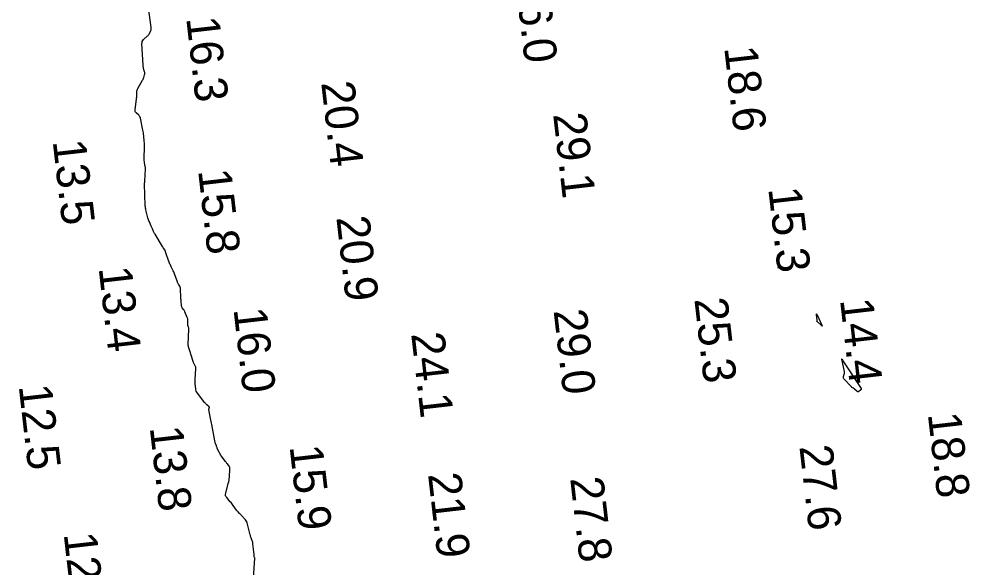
# Model space of a CAD drawing. Extents: x 1023796 to 1112670, y 656573 to 837340.
# Drawn here: x 1109716.8 to 1109860.7, y 681529.2 to 681612.4 of the extents above; entities that cross this region are included whole.
import ezdxf

# ---------------------------------------------------------------- set-up
doc = ezdxf.new("R2010")
doc.units = 0
doc.layers.add('V-CHAN-CONT-15FT', color=7, linetype='Continuous')
doc.layers.add('V-TOPO-SOUN', color=7, linetype='Continuous')

msp = doc.modelspace()

# ---------------------------------------------------------------- linework, layer by layer
at = {"layer": 'V-CHAN-CONT-15FT'}
msp.add_lwpolyline([(1109752.25, 681526.93), (1109752.47, 681530.72), (1109752.47, 681530.75), (1109752.47, 681530.78), (1109752.46, 681530.8), (1109752.45, 681530.83), (1109752.4, 681530.92), (1109752.39, 681530.95), (1109752.38, 681530.97), (1109752.38, 681531), (1109752.38, 681531.03), (1109752.39, 681531.15), (1109752.39, 681531.18), (1109752.39, 681531.21), (1109752.39, 681531.24), (1109752.39, 681531.27), (1109752.2, 681532.92), (1109752.18, 681533.03), (1109752.16, 681533.15), (1109752.12, 681533.26), (1109752.08, 681533.37), (1109751.91, 681533.81), (1109751.87, 681533.92), (1109751.83, 681534.03), (1109751.8, 681534.14), (1109751.77, 681534.26), (1109751.39, 681535.89), (1109751.34, 681536.07), (1109751.26, 681536.23), (1109751.17, 681536.39), (1109751.05, 681536.54), (1109750.4, 681537.26), (1109750.34, 681537.32), (1109750.29, 681537.38), (1109750.23, 681537.44), (1109750.17, 681537.5), (1109749.94, 681537.73), (1109749.88, 681537.79), (1109749.83, 681537.85), (1109749.77, 681537.91), (1109749.72, 681537.98), (1109749.2, 681538.71), (1109749.09, 681538.85), (1109748.98, 681538.99), (1109748.87, 681539.13), (1109748.76, 681539.26), (1109748.22, 681539.89), (1109748.11, 681540.05), (1109748.05, 681540.21), (1109748.04, 681540.39), (1109748.07, 681540.57), (1109748.46, 681542.04), (1109748.52, 681542.28), (1109748.57, 681542.52), (1109748.6, 681542.76), (1109748.62, 681543.01), (1109748.7, 681544.26), (1109748.7, 681544.36), (1109748.68, 681544.46), (1109748.64, 681544.56), (1109748.58, 681544.65), (1109748.32, 681545), (1109748.26, 681545.08), (1109748.19, 681545.17), (1109748.13, 681545.26), (1109748.06, 681545.34), (1109747.4, 681546.22), (1109747.31, 681546.34), (1109747.23, 681546.47), (1109747.16, 681546.6), (1109747.09, 681546.73), (1109746.8, 681547.37), (1109746.76, 681547.46), (1109746.72, 681547.55), (1109746.68, 681547.64), (1109746.65, 681547.73), (1109746.52, 681548.1), (1109746.49, 681548.19), (1109746.46, 681548.28), (1109746.43, 681548.38), (1109746.41, 681548.47), (1109745.96, 681550.95), (1109745.92, 681551.19), (1109745.87, 681551.42), (1109745.83, 681551.66), (1109745.79, 681551.89), (1109745.53, 681553.22), (1109745.52, 681553.26), (1109745.52, 681553.29), (1109745.53, 681553.33), (1109745.54, 681553.36), (1109745.58, 681553.51), (1109745.59, 681553.54), (1109745.59, 681553.57), (1109745.57, 681553.6), (1109745.55, 681553.63), (1109745.19, 681553.96), (1109745.12, 681554.03), (1109745.05, 681554.1), (1109744.99, 681554.17), (1109744.93, 681554.24), (1109743.79, 681555.71), (1109743.69, 681555.86), (1109743.62, 681556.02), (1109743.56, 681556.19), (1109743.53, 681556.37), (1109743.47, 681557.1), (1109743.45, 681557.28), (1109743.45, 681557.46), (1109743.45, 681557.64), (1109743.46, 681557.83), (1109743.57, 681559.4), (1109743.57, 681559.49), (1109743.55, 681559.57), (1109743.53, 681559.65), (1109743.49, 681559.73), (1109743.32, 681560.03), (1109743.28, 681560.1), (1109743.25, 681560.18), (1109743.22, 681560.26), (1109743.19, 681560.34), (1109742.8, 681561.61), (1109742.76, 681561.73), (1109742.72, 681561.86), (1109742.68, 681561.98), (1109742.64, 681562.1), (1109742.48, 681562.59), (1109742.45, 681562.71), (1109742.42, 681562.84), (1109742.41, 681562.96), (1109742.41, 681563.09), (1109742.51, 681565.41), (1109742.51, 681565.48), (1109742.5, 681565.55), (1109742.49, 681565.62), (1109742.46, 681565.69), (1109742.36, 681565.96), (1109742.33, 681566.03), (1109742.32, 681566.1), (1109742.31, 681566.17), (1109742.31, 681566.24), (1109742.33, 681566.76), (1109742.33, 681566.87), (1109742.32, 681566.97), (1109742.29, 681567.08), (1109742.25, 681567.18), (1109741.9, 681568.01), (1109741.86, 681568.09), (1109741.82, 681568.17), (1109741.77, 681568.25), (1109741.72, 681568.33), (1109741.5, 681568.63), (1109741.45, 681568.71), (1109741.41, 681568.79), (1109741.39, 681568.88), (1109741.37, 681568.97), (1109741.33, 681569.59), (1109741.32, 681569.73), (1109741.31, 681569.86), (1109741.3, 681570), (1109741.29, 681570.14), (1109741.22, 681571.56), (1109741.21, 681571.65), (1109741.19, 681571.73), (1109741.15, 681571.82), (1109741.11, 681571.9), (1109740.91, 681572.21), (1109740.87, 681572.29), (1109740.83, 681572.37), (1109740.79, 681572.45), (1109740.76, 681572.54), (1109740.38, 681573.61), (1109740.33, 681573.77), (1109740.26, 681573.92), (1109740.2, 681574.07), (1109740.13, 681574.22), (1109739.81, 681574.86), (1109739.75, 681574.99), (1109739.69, 681575.13), (1109739.63, 681575.26), (1109739.58, 681575.4), (1109739.37, 681575.97), (1109739.32, 681576.1), (1109739.27, 681576.23), (1109739.23, 681576.36), (1109739.18, 681576.49), (1109738.97, 681577.12), (1109738.95, 681577.19), (1109738.92, 681577.26), (1109738.88, 681577.33), (1109738.84, 681577.39), (1109738.67, 681577.65), (1109738.62, 681577.71), (1109738.58, 681577.78), (1109738.54, 681577.85), (1109738.5, 681577.91), (1109737.37, 681579.8), (1109737.31, 681579.9), (1109737.26, 681579.99), (1109737.21, 681580.09), (1109737.16, 681580.19), (1109736.97, 681580.59), (1109736.93, 681580.69), (1109736.88, 681580.79), (1109736.84, 681580.89), (1109736.79, 681580.99), (1109736.51, 681581.67), (1109736.45, 681581.81), (1109736.4, 681581.96), (1109736.35, 681582.12), (1109736.3, 681582.27), (1109736, 681583.47), (1109735.98, 681583.53), (1109735.97, 681583.58), (1109735.96, 681583.63), (1109735.95, 681583.69), (1109735.91, 681583.91), (1109735.91, 681583.96), (1109735.9, 681584.02), (1109735.9, 681584.07), (1109735.89, 681584.13), (1109735.79, 681587.34), (1109735.79, 681587.38), (1109735.8, 681587.42), (1109735.8, 681587.46), (1109735.8, 681587.5), (1109735.83, 681587.65), (1109735.84, 681587.69), (1109735.84, 681587.73), (1109735.84, 681587.77), (1109735.85, 681587.82), (1109735.92, 681589.61), (1109735.92, 681589.7), (1109735.92, 681589.79), (1109735.91, 681589.88), (1109735.89, 681589.97), (1109735.83, 681590.32), (1109735.81, 681590.4), (1109735.8, 681590.49), (1109735.78, 681590.57), (1109735.77, 681590.66), (1109735.72, 681591), (1109735.71, 681591.09), (1109735.7, 681591.17), (1109735.7, 681591.26), (1109735.7, 681591.35), (1109735.76, 681592.93), (1109735.76, 681593.15), (1109735.76, 681593.37), (1109735.75, 681593.59), (1109735.74, 681593.8), (1109735.67, 681594.68), (1109735.64, 681594.9), (1109735.61, 681595.12), (1109735.58, 681595.33), (1109735.54, 681595.55), (1109735.15, 681597.37), (1109735.12, 681597.49), (1109735.06, 681597.61), (1109734.99, 681597.71), (1109734.9, 681597.8), (1109734.51, 681598.15), (1109734.43, 681598.25), (1109734.38, 681598.35), (1109734.35, 681598.47), (1109734.35, 681598.59), (1109734.57, 681600.25), (1109734.58, 681600.38), (1109734.59, 681600.52), (1109734.6, 681600.66), (1109734.61, 681600.8), (1109734.62, 681601.35), (1109734.63, 681601.48), (1109734.66, 681601.61), (1109734.7, 681601.74), (1109734.77, 681601.86), (1109735.49, 681603.1), (1109735.55, 681603.2), (1109735.59, 681603.3), (1109735.63, 681603.4), (1109735.67, 681603.51), (1109735.79, 681603.93), (1109735.82, 681604.04), (1109735.83, 681604.15), (1109735.82, 681604.26), (1109735.79, 681604.36), (1109735.64, 681604.88), (1109735.61, 681605.01), (1109735.59, 681605.13), (1109735.57, 681605.26), (1109735.56, 681605.38), (1109735.39, 681608.65), (1109735.4, 681608.82), (1109735.44, 681608.97), (1109735.52, 681609.11), (1109735.63, 681609.24), (1109736.23, 681609.79), (1109736.32, 681609.88), (1109736.39, 681609.97), (1109736.46, 681610.07), (1109736.52, 681610.18), (1109736.72, 681610.63), (1109736.77, 681610.74), (1109736.79, 681610.85), (1109736.8, 681610.97), (1109736.79, 681611.09), (1109736.37, 681614.03)], dxfattribs=at)
for points in [[(1109831.67, 681574.7), (1109831.67, 681574.7), (1109831.67, 681574.7), (1109831.76, 681574.74), (1109831.77, 681574.74), (1109831.78, 681574.74), (1109831.78, 681574.74), (1109831.77, 681574.73), (1109831.71, 681574.68), (1109831.71, 681574.68), (1109831.71, 681574.68), (1109831.71, 681574.67), (1109831.7, 681574.67), (1109831.69, 681574.67), (1109831.68, 681574.67), (1109831.68, 681574.67), (1109831.66, 681574.67), (1109831.66, 681574.67), (1109831.66, 681574.69), (1109831.66, 681574.7)], [(1109837.53, 681567.7), (1109837.56, 681567.67), (1109837.61, 681567.58), (1109838.34, 681566.02), (1109838.39, 681565.91), (1109838.38, 681565.86), (1109838.34, 681565.87), (1109838.25, 681565.95), (1109837.6, 681566.55), (1109837.58, 681566.57), (1109837.58, 681566.59), (1109837.57, 681566.61), (1109837.58, 681566.63), (1109837.6, 681566.72), (1109837.61, 681566.74), (1109837.61, 681566.77), (1109837.61, 681566.79), (1109837.61, 681566.81), (1109837.53, 681567.56), (1109837.52, 681567.66)], [(1109841.75, 681558.8), (1109841.75, 681558.89), (1109841.73, 681558.99), (1109841.32, 681560.84), (1109841.31, 681560.87), (1109841.32, 681560.88), (1109841.33, 681560.87), (1109841.34, 681560.85), (1109841.44, 681560.71), (1109841.49, 681560.62), (1109844.25, 681556.4), (1109844.28, 681556.34), (1109844.28, 681556.29), (1109844.26, 681556.24), (1109844.22, 681556.19), (1109843.88, 681555.93), (1109843.88, 681555.93), (1109843.87, 681555.93), (1109843.86, 681555.92), (1109843.85, 681555.92), (1109843.81, 681555.92), (1109843.81, 681555.93), (1109843.8, 681555.93), (1109843.79, 681555.93), (1109843.78, 681555.93), (1109843.72, 681555.94), (1109843.7, 681555.95), (1109843.69, 681555.95), (1109843.68, 681555.96), (1109843.67, 681555.97), (1109843.28, 681556.33), (1109843.27, 681556.35), (1109843.26, 681556.36), (1109843.24, 681556.37), (1109843.23, 681556.38), (1109843.18, 681556.42), (1109843.16, 681556.43), (1109843.15, 681556.44), (1109843.13, 681556.44), (1109843.12, 681556.45), (1109842.95, 681556.52), (1109842.92, 681556.53), (1109842.89, 681556.55), (1109842.86, 681556.57), (1109842.84, 681556.6), (1109841.66, 681557.88), (1109841.61, 681557.96), (1109841.58, 681558.04), (1109841.57, 681558.13), (1109841.59, 681558.22), (1109841.71, 681558.6), (1109841.74, 681558.7)]]:
    msp.add_lwpolyline(points, close=True, dxfattribs=at)

# ---------------------------------------------------------------- texts
at = {"layer": 'V-TOPO-SOUN'}
for s, p in [('26.0 ', (1109791.89, 681618.41)), ('16.3 ', (1109742.08, 681612.5)), ('18.6 ', (1109823.53, 681608.03)), ('20.4 ', (1109762.52, 681602.72)), ('29.1 ', (1109797.63, 681597.94)), ('13.5 ', (1109721.87, 681593.87)), ('15.8 ', (1109743.88, 681589.43)), ('15.3 ', (1109830.2, 681586.68)), ('20.9 ', (1109764.81, 681582.32)), ('13.4 ', (1109728.82, 681574.67)), ('25.3 ', (1109819.01, 681569.95)), ('14.4 ', (1109841.06, 681569.85)), ('16.0 ', (1109749.24, 681568.44)), ('29.0 ', (1109797.7, 681568.21)), ('24.1 ', (1109776.14, 681564.7)), ('12.5 ', (1109716.72, 681556.8)), ('18.8 ', (1109854.35, 681552.56)), ('13.8 ', (1109736.56, 681550.52)), ('15.9 ', (1109757.73, 681547.64)), ('27.6 ', (1109834.91, 681547.63)), ('21.9 ', (1109778.69, 681543.44)), ('27.8 ', (1109800.21, 681542.81)), ('12.6 ', (1109723.53, 681534.4))]:
    msp.add_text(s, height=5, rotation=276.5594, dxfattribs=at).set_placement(p)

doc.saveas('drawing.dxf')
